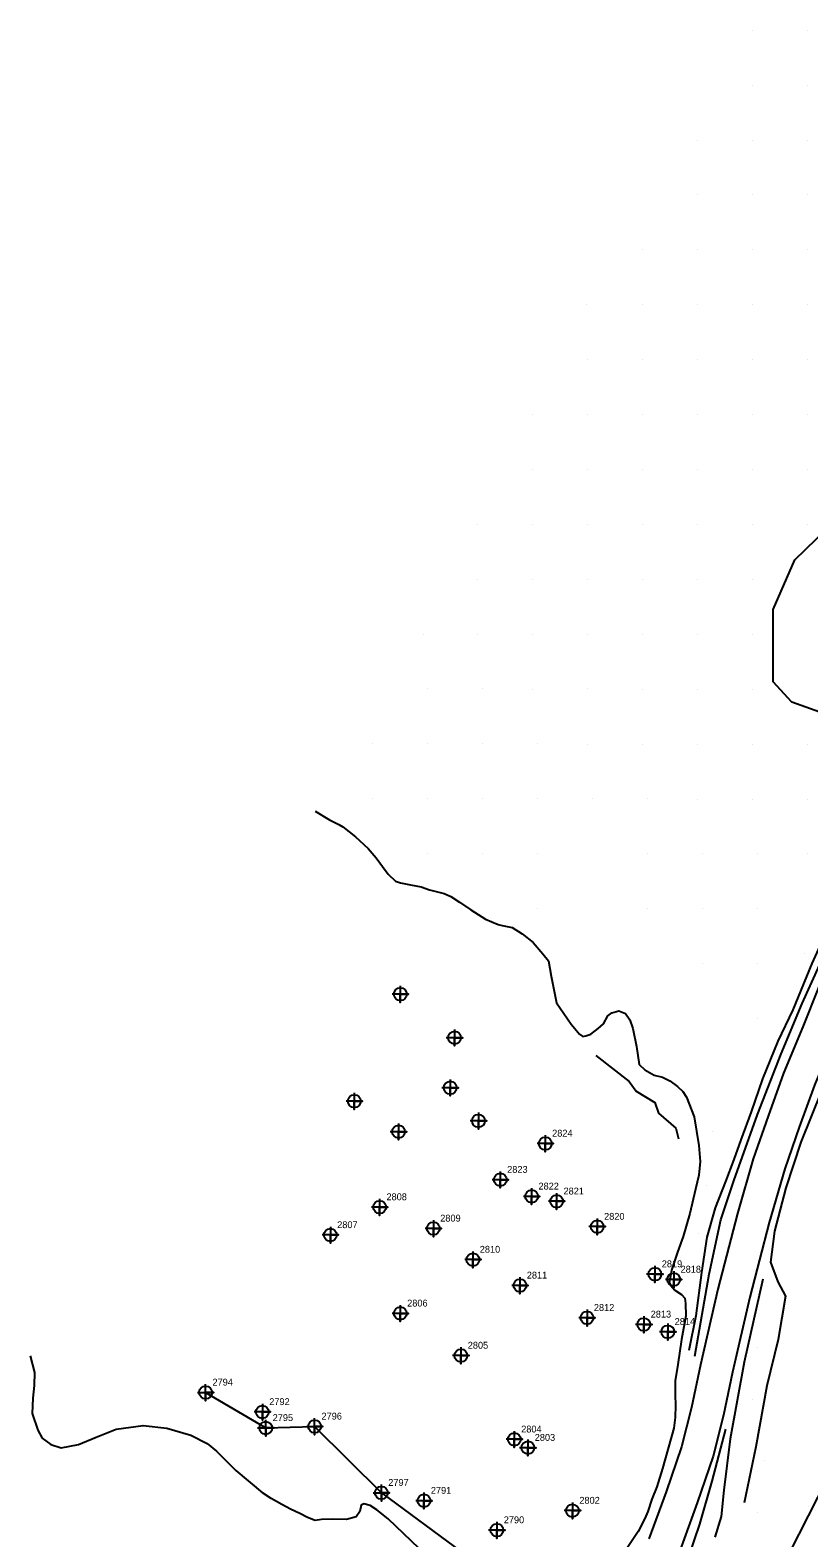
# Model space of a CAD drawing. Extents: x 2062781 to 2066835, y 358981 to 366501.
# Drawn here: x 2064554 to 2064838, y 362990 to 363540 of the extents above; entities that cross this region are included whole.
import ezdxf

# ---------------------------------------------------------------- set-up
doc = ezdxf.new("R2010")
doc.units = 0
for name, color, linetype in [('Exist DTM Regular Point CELL', 7, 'Continuous'), ('Exist DTM Regular Point Cogo Number', 7, 'Continuous'), ('Exist DTM Regular Point Underwater CELL', 7, 'Continuous'), ('Exist DTM Regular Point Underwater Cogo Number', 7, 'Continuous'), ('Exist Hydro Stream or Body of Water', 7, 'Continuous'), ('Exist Hydro Stream or Body of Water Cogo Number', 7, 'Continuous'), ('Exist Hydro Stream or Body of Water Cogo Point CELL', 7, 'Continuous'), ('Exist Structure Major Deck Tunnel Box Culvert', 7, 'Continuous'), ('PH Exist DTM Breakline', 7, 'Continuous'), ('PH Exist DTM Point', 7, 'Continuous')]:
    doc.layers.add(name, color=color, linetype=linetype)

msp = doc.modelspace()

# ---------------------------------------------------------------- linework, layer by layer
at = {"layer": 'Exist DTM Regular Point CELL'}
for points in [[(2064788.45, 363087.54), (2064788.45, 363081.54), (2064788.45, 363084.54), (2064791.45, 363084.54), (2064785.45, 363084.54)], [(2064786.3, 363068.49), (2064786.3, 363062.49), (2064786.3, 363065.49), (2064789.3, 363065.49), (2064783.3, 363065.49)]]:
    msp.add_lwpolyline(points, dxfattribs=at)
for centre in [(2064788.45, 363084.54), (2064786.3, 363065.49)]:
    msp.add_circle(centre, 2.34, dxfattribs=at)
at = {"layer": 'Exist DTM Regular Point Underwater CELL'}
for points in [[(2064688.89, 363191.46), (2064688.89, 363185.46), (2064688.89, 363188.46), (2064691.89, 363188.46), (2064685.89, 363188.46)], [(2064708.64, 363175.6), (2064708.64, 363169.6), (2064708.64, 363172.6), (2064711.64, 363172.6), (2064705.64, 363172.6)], [(2064707.05, 363157.38), (2064707.05, 363151.38), (2064707.05, 363154.38), (2064710.05, 363154.38), (2064704.05, 363154.38)], [(2064672.13, 363152.51), (2064672.13, 363146.51), (2064672.13, 363149.51), (2064675.13, 363149.51), (2064669.13, 363149.51)], [(2064717.35, 363145.34), (2064717.35, 363139.34), (2064717.35, 363142.34), (2064720.35, 363142.34), (2064714.35, 363142.34)], [(2064688.25, 363141.37), (2064688.25, 363135.37), (2064688.25, 363138.37), (2064691.25, 363138.37), (2064685.25, 363138.37)], [(2064741.68, 363137.09), (2064741.68, 363131.09), (2064741.68, 363134.09), (2064744.68, 363134.09), (2064738.68, 363134.09)], [(2064725.31, 363123.9), (2064725.31, 363117.9), (2064725.31, 363120.9), (2064728.31, 363120.9), (2064722.31, 363120.9)], [(2064736.7, 363117.82), (2064736.7, 363111.82), (2064736.7, 363114.82), (2064739.7, 363114.82), (2064733.7, 363114.82)], [(2064745.82, 363116.02), (2064745.82, 363110.02), (2064745.82, 363113.02), (2064748.82, 363113.02), (2064742.82, 363113.02)], [(2064681.35, 363113.92), (2064681.35, 363107.92), (2064681.35, 363110.92), (2064684.35, 363110.92), (2064678.35, 363110.92)], [(2064700.93, 363106.15), (2064700.93, 363100.15), (2064700.93, 363103.15), (2064703.93, 363103.15), (2064697.93, 363103.15)], [(2064760.6, 363106.8), (2064760.6, 363100.8), (2064760.6, 363103.8), (2064763.6, 363103.8), (2064757.6, 363103.8)], [(2064663.41, 363103.76), (2064663.41, 363097.76), (2064663.41, 363100.76), (2064666.41, 363100.76), (2064660.41, 363100.76)], [(2064715.33, 363094.8), (2064715.33, 363088.8), (2064715.33, 363091.8), (2064718.33, 363091.8), (2064712.33, 363091.8)], [(2064781.6, 363089.51), (2064781.6, 363083.51), (2064781.6, 363086.51), (2064784.6, 363086.51), (2064778.6, 363086.51)], [(2064732.45, 363085.39), (2064732.45, 363079.39), (2064732.45, 363082.39), (2064735.45, 363082.39), (2064729.45, 363082.39)], [(2064688.89, 363075.21), (2064688.89, 363069.21), (2064688.89, 363072.21), (2064691.89, 363072.21), (2064685.89, 363072.21)], [(2064756.88, 363073.61), (2064756.88, 363067.61), (2064756.88, 363070.61), (2064759.88, 363070.61), (2064753.88, 363070.61)], [(2064777.57, 363071.19), (2064777.57, 363065.19), (2064777.57, 363068.19), (2064780.57, 363068.19), (2064774.57, 363068.19)], [(2064710.95, 363059.86), (2064710.95, 363053.86), (2064710.95, 363056.86), (2064713.95, 363056.86), (2064707.95, 363056.86)], [(2064638.67, 363039.32), (2064638.67, 363033.32), (2064638.67, 363036.32), (2064641.67, 363036.32), (2064635.67, 363036.32)], [(2064730.41, 363029.35), (2064730.41, 363023.35), (2064730.41, 363026.35), (2064733.41, 363026.35), (2064727.41, 363026.35)], [(2064735.34, 363026.3), (2064735.34, 363020.3), (2064735.34, 363023.3), (2064738.34, 363023.3), (2064732.34, 363023.3)], [(2064697.51, 363007.01), (2064697.51, 363001.01), (2064697.51, 363004.01), (2064700.51, 363004.01), (2064694.51, 363004.01)], [(2064751.59, 363003.39), (2064751.59, 362997.39), (2064751.59, 363000.39), (2064754.59, 363000.39), (2064748.59, 363000.39)], [(2064724.06, 362996.29), (2064724.06, 362990.29), (2064724.06, 362993.29), (2064727.06, 362993.29), (2064721.06, 362993.29)]]:
    msp.add_lwpolyline(points, dxfattribs=at)
for centre in [(2064688.89, 363188.46), (2064708.64, 363172.6), (2064707.05, 363154.38), (2064672.13, 363149.51), (2064717.35, 363142.34), (2064688.25, 363138.37), (2064741.68, 363134.09), (2064725.31, 363120.9), (2064736.7, 363114.82), (2064745.82, 363113.02), (2064681.35, 363110.92), (2064700.93, 363103.15), (2064760.6, 363103.8), (2064663.41, 363100.76), (2064715.33, 363091.8), (2064781.6, 363086.51), (2064732.45, 363082.39), (2064688.89, 363072.21), (2064756.88, 363070.61), (2064777.57, 363068.19), (2064710.95, 363056.86), (2064638.67, 363036.32), (2064730.41, 363026.35), (2064735.34, 363023.3), (2064697.51, 363004.01), (2064751.59, 363000.39), (2064724.06, 362993.29)]:
    msp.add_circle(centre, 2.34, dxfattribs=at)
at = {"layer": 'Exist Hydro Stream or Body of Water'}
for points in [[(2064760.13, 363166.13), (2064772.23, 363156.64), (2064774.78, 363153.16), (2064781.59, 363149.01), (2064782.97, 363145.09), (2064789.28, 363139.67), (2064790.17, 363135.72)], [(2064617.98, 363043.42), (2064639.91, 363030.5), (2064657.69, 363031.04), (2064682, 363006.89), (2064711.34, 362985.3), (2064723.86, 362974.82), (2064739.34, 362964.04)]]:
    msp.add_lwpolyline(points, dxfattribs=at)
at = {"layer": 'Exist Hydro Stream or Body of Water Cogo Point CELL'}
for points in [[(2064614.98, 363043.42), (2064620.98, 363043.42), (2064617.98, 363043.42), (2064617.98, 363040.42), (2064617.98, 363046.42)], [(2064614.98, 363043.42), (2064620.98, 363043.42), (2064617.98, 363043.42), (2064617.98, 363040.42), (2064617.98, 363046.42)], [(2064614.98, 363043.42), (2064620.98, 363043.42), (2064617.98, 363043.42), (2064617.98, 363040.42), (2064617.98, 363046.42)], [(2064636.91, 363030.5), (2064642.91, 363030.5), (2064639.91, 363030.5), (2064639.91, 363027.5), (2064639.91, 363033.5)], [(2064636.91, 363030.5), (2064642.91, 363030.5), (2064639.91, 363030.5), (2064639.91, 363027.5), (2064639.91, 363033.5)], [(2064636.91, 363030.5), (2064642.91, 363030.5), (2064639.91, 363030.5), (2064639.91, 363027.5), (2064639.91, 363033.5)], [(2064654.69, 363031.04), (2064660.69, 363031.04), (2064657.69, 363031.04), (2064657.69, 363028.04), (2064657.69, 363034.04)], [(2064654.69, 363031.04), (2064660.69, 363031.04), (2064657.69, 363031.04), (2064657.69, 363028.04), (2064657.69, 363034.04)], [(2064654.69, 363031.04), (2064660.69, 363031.04), (2064657.69, 363031.04), (2064657.69, 363028.04), (2064657.69, 363034.04)], [(2064679, 363006.89), (2064685, 363006.89), (2064682, 363006.89), (2064682, 363003.89), (2064682, 363009.89)], [(2064679, 363006.89), (2064685, 363006.89), (2064682, 363006.89), (2064682, 363003.89), (2064682, 363009.89)], [(2064679, 363006.89), (2064685, 363006.89), (2064682, 363006.89), (2064682, 363003.89), (2064682, 363009.89)]]:
    msp.add_lwpolyline(points, dxfattribs=at)
for centre in [(2064617.98, 363043.42), (2064617.98, 363043.42), (2064617.98, 363043.42), (2064639.91, 363030.5), (2064639.91, 363030.5), (2064639.91, 363030.5), (2064657.69, 363031.04), (2064657.69, 363031.04), (2064657.69, 363031.04), (2064682, 363006.89), (2064682, 363006.89), (2064682, 363006.89)]:
    msp.add_circle(centre, 2.34, dxfattribs=at)
at = {"layer": 'Exist Structure Major Deck Tunnel Box Culvert'}
msp.add_lwpolyline([(2064623.4, 362577.44), (2064650.62, 362630.92), (2064677.82, 362684.31), (2064698.23, 362724.56), (2064718.6, 362764.59), (2064738.99, 362804.71), (2064759.36, 362844.81), (2064779.84, 362884.94), (2064800.12, 362924.98), (2064820.56, 362965.07), (2064840.94, 363005.22), (2064861.36, 363045.25), (2064881.68, 363085.34), (2064902.1, 363125.46), (2064922.64, 363165.68)], dxfattribs=at)
at = {"layer": 'PH Exist DTM Breakline'}
for points in [[(2064843.33, 363290.6), (2064831.49, 363294.81), (2064824.68, 363302.18), (2064824.62, 363328.54), (2064832.53, 363346.69), (2064844.5, 363358.16)], [(2064657.92, 363255.13), (2064663.09, 363251.94), (2064666.55, 363250.21), (2064667.94, 363249.45), (2064672.63, 363245.78), (2064677.14, 363241.5), (2064680.09, 363238.15), (2064682.43, 363234.95), (2064684.41, 363232.16), (2064687.1, 363229.67), (2064689.01, 363228.99), (2064692.59, 363228.3), (2064696.52, 363227.55), (2064699.57, 363226.47), (2064704.82, 363225.15), (2064707.28, 363224.04), (2064710.44, 363221.98), (2064714.59, 363219.2), (2064719.91, 363215.83), (2064724.51, 363213.84), (2064725.99, 363213.41), (2064729.67, 363212.71), (2064733.32, 363210.38), (2064737.29, 363207.26), (2064740.76, 363203.11), (2064742.81, 363200.63), (2064743.84, 363194.98), (2064745.82, 363185.25), (2064751.16, 363177.59), (2064754.2, 363173.91), (2064755.33, 363173.09), (2064756.45, 363173.32), (2064758.25, 363173.95), (2064760.92, 363175.9), (2064762.83, 363177.68), (2064764.48, 363180.52), (2064765.95, 363181.68), (2064768.48, 363182.37), (2064770.87, 363181.41), (2064772.48, 363179.06), (2064773.6, 363175.9), (2064774.95, 363169.35), (2064775.92, 363162.85), (2064777.92, 363160.93), (2064781.3, 363158.95), (2064784.4, 363158.25), (2064787.04, 363156.88), (2064789.83, 363154.89), (2064791.73, 363153.06), (2064793.05, 363150.99), (2064795.86, 363143.75), (2064797.66, 363133.36), (2064798.12, 363127.49), (2064797.54, 363122.52), (2064796.33, 363117.48), (2064794.31, 363108.61), (2064791.88, 363100.18), (2064789.87, 363094.56), (2064787.72, 363088.34), (2064786.85, 363083.47), (2064787.46, 363082.36), (2064788.87, 363080.66), (2064791.24, 363079.11), (2064792.48, 363077.7), (2064792.79, 363075.86), (2064792.91, 363071.27), (2064791.34, 363062.69), (2064789.94, 363053.64), (2064789.04, 363047.69), (2064789.03, 363042.51), (2064789.08, 363038.62), (2064788.93, 363034.34), (2064788.48, 363030.46), (2064784.35, 363015.67), (2064782.35, 363009.03), (2064780.47, 363004.5), (2064779.02, 363000.05), (2064777.89, 362997.57), (2064775.49, 362992.81), (2064770.64, 362985.56)], [(2064862.71, 363237.07), (2064853.51, 363218.29), (2064848.01, 363206.24), (2064841.2, 363190.87), (2064835.47, 363176.54), (2064828.48, 363159.64), (2064822.82, 363144.06), (2064817.42, 363128.52), (2064811.62, 363108.55), (2064804.49, 363081.02), (2064798.19, 363053.42), (2064794.93, 363037.88), (2064791.27, 363023.67), (2064785.71, 363007.19), (2064779.45, 362990.06)], [(2064873.49, 363231.78), (2064864.35, 363213.16), (2064858.95, 363201.32), (2064852.26, 363186.21), (2064846.59, 363172.02), (2064839.67, 363155.29), (2064834.13, 363140.04), (2064828.86, 363124.88), (2064823.2, 363105.37), (2064816.15, 363078.18), (2064809.91, 363050.85), (2064806.62, 363035.15), (2064802.78, 363020.25), (2064797.04, 363003.22), (2064790.66, 362985.76)], [(2064853.69, 363231.16), (2064846.39, 363216.49), (2064838.69, 363199.61), (2064831.8, 363182.7), (2064826.4, 363171.33), (2064820.73, 363157.67), (2064816.63, 363145.64), (2064812.94, 363135.45), (2064810.32, 363128.26), (2064807.3, 363120.23), (2064803.49, 363110.63), (2064800.46, 363099.95), (2064798.58, 363087.12), (2064796.5, 363071.29), (2064793.9, 363058.66)], [(2064796.12, 363056.59), (2064801.37, 363086.52), (2064805.6, 363106.33), (2064810.36, 363120.49), (2064819, 363144.64), (2064827.58, 363166.72), (2064835.24, 363185.04), (2064841.66, 363199.26), (2064848.43, 363213.73), (2064855.43, 363227.48)], [(2064871.4, 363223.84), (2064863.73, 363207.42), (2064856.68, 363192.23), (2064849.57, 363172.94), (2064842.21, 363153.26), (2064834.74, 363134.62), (2064829.26, 363117.95), (2064825.16, 363102.2), (2064823.75, 363090.82), (2064826.39, 363083.66), (2064829.2, 363078.52), (2064826.43, 363062.75), (2064822.32, 363045.89), (2064818.41, 363023.67), (2064814.05, 363003.28)], [(2064820.94, 363084.71), (2064814.16, 363054.4), (2064809.06, 363026.54), (2064806.69, 363007.85), (2064805.77, 362998.28), (2064803.47, 362990.71)], [(2064554.1, 363056.73), (2064555.71, 363050.64), (2064555.55, 363046.01), (2064555.05, 363041.31), (2064554.89, 363035.71), (2064556.87, 363029.74), (2064558.43, 363026.8), (2064561.63, 363024.44), (2064565.35, 363023.22), (2064571.7, 363024.51), (2064578.18, 363027.14), (2064585.47, 363030.04), (2064595.28, 363031.4), (2064603.88, 363030.39), (2064612.56, 363027.86), (2064618.61, 363024.84), (2064621.96, 363022.04), (2064628.95, 363014.99), (2064638.74, 363006.82)], [(2064807.3, 363030.11), (2064802.32, 363011.11), (2064797.84, 362995.47), (2064791.78, 362977.67), (2064781.44, 362953.56), (2064768.13, 362924.72), (2064754.4, 362897.09), (2064735.4, 362860.89), (2064708.55, 362807.94), (2064678.24, 362751.31), (2064659.16, 362714.52), (2064643.7, 362686.38), (2064628.13, 362658.09), (2064617.21, 362639.02), (2064609.98, 362625.86), (2064598.02, 362605.33), (2064591.98, 362596.35), (2064587.07, 362588.82), (2064583.37, 362583.25)], [(2064695.66, 362986.75), (2064690.17, 362991.9), (2064684.52, 362997.38), (2064680.32, 363000.7), (2064677.93, 363002.22), (2064675.62, 363002.84), (2064674.61, 363002.33), (2064674.15, 363000.09), (2064672.83, 362998.15), (2064669.24, 362997.15), (2064664.17, 362997.23), (2064660.24, 362997.13), (2064657.92, 362996.75), (2064655.06, 362997.83), (2064652.6, 362999.16), (2064648.96, 363000.86), (2064645.77, 363002.62), (2064641.9, 363004.81), (2064638.74, 363006.82)]]:
    msp.add_lwpolyline(points, dxfattribs=at)
at = {"layer": 'PH Exist DTM Point'}
for p, q in [((2064817.11, 363539.52), (2064817.11, 363539.52)), ((2064837.11, 363539.52), (2064837.11, 363539.52)), ((2064817.11, 363519.52), (2064817.11, 363519.52)), ((2064837.11, 363519.52), (2064837.11, 363519.52)), ((2064797.11, 363499.52), (2064797.11, 363499.52)), ((2064817.11, 363499.52), (2064817.11, 363499.52)), ((2064837.11, 363499.52), (2064837.11, 363499.52)), ((2064797.11, 363479.52), (2064797.11, 363479.52)), ((2064817.06, 363479.61), (2064817.06, 363479.61)), ((2064837.11, 363479.52), (2064837.11, 363479.52)), ((2064777.11, 363459.52), (2064777.11, 363459.52)), ((2064797.11, 363459.52), (2064797.11, 363459.52)), ((2064817.11, 363459.52), (2064817.11, 363459.52)), ((2064837.11, 363459.52), (2064837.11, 363459.52)), ((2064756.69, 363439.7), (2064756.69, 363439.7)), ((2064777.11, 363439.52), (2064777.11, 363439.52)), ((2064797.11, 363439.52), (2064797.11, 363439.52)), ((2064817.11, 363439.52), (2064817.11, 363439.52)), ((2064837.11, 363439.52), (2064837.11, 363439.52)), ((2064757.11, 363419.52), (2064757.11, 363419.52)), ((2064777.11, 363419.52), (2064777.11, 363419.52)), ((2064797.11, 363419.52), (2064797.11, 363419.52)), ((2064817.11, 363419.52), (2064817.11, 363419.52)), ((2064837.11, 363419.52), (2064837.11, 363419.52)), ((2064736.97, 363399.72), (2064736.97, 363399.72)), ((2064757.11, 363399.52), (2064757.11, 363399.52)), ((2064777.11, 363399.52), (2064777.11, 363399.52)), ((2064797.11, 363399.52), (2064797.11, 363399.52)), ((2064817.11, 363399.52), (2064817.11, 363399.52)), ((2064837.16, 363399.52), (2064837.16, 363399.52)), ((2064737.16, 363379.62), (2064737.16, 363379.62)), ((2064757.11, 363379.52), (2064757.11, 363379.52)), ((2064777.11, 363379.52), (2064777.11, 363379.52)), ((2064797.11, 363379.52), (2064797.11, 363379.52)), ((2064817.11, 363379.52), (2064817.11, 363379.52)), ((2064837.11, 363379.52), (2064837.11, 363379.52)), ((2064717.11, 363359.52), (2064717.11, 363359.52)), ((2064737.11, 363359.52), (2064737.11, 363359.52)), ((2064757.11, 363359.52), (2064757.11, 363359.52)), ((2064777.11, 363359.52), (2064777.11, 363359.52)), ((2064797.11, 363359.52), (2064797.11, 363359.52)), ((2064817.11, 363359.52), (2064817.11, 363359.52)), ((2064837.11, 363359.52), (2064837.11, 363359.52)), ((2064717.11, 363339.52), (2064717.11, 363339.52)), ((2064737.11, 363339.52), (2064737.11, 363339.52)), ((2064757.11, 363339.52), (2064757.11, 363339.52)), ((2064777.11, 363339.52), (2064777.11, 363339.52)), ((2064797.11, 363339.52), (2064797.11, 363339.52)), ((2064817.11, 363339.52), (2064817.11, 363339.52)), ((2064697.25, 363319.57), (2064697.25, 363319.57)), ((2064717.11, 363319.52), (2064717.11, 363319.52)), ((2064737.11, 363319.52), (2064737.11, 363319.52)), ((2064757.11, 363319.52), (2064757.11, 363319.52)), ((2064777.11, 363319.52), (2064777.11, 363319.52)), ((2064797.11, 363319.52), (2064797.11, 363319.52)), ((2064817.11, 363319.52), (2064817.11, 363319.52)), ((2064698.86, 363299.76), (2064698.86, 363299.76)), ((2064718.86, 363299.76), (2064718.86, 363299.76)), ((2064737.11, 363299.52), (2064737.11, 363299.52)), ((2064757.04, 363299.62), (2064757.04, 363299.62)), ((2064777.11, 363299.52), (2064777.11, 363299.52)), ((2064797.11, 363299.52), (2064797.11, 363299.52)), ((2064817.12, 363299.55), (2064817.12, 363299.55)), ((2064678.8, 363279.74), (2064678.8, 363279.74)), ((2064698.86, 363279.76), (2064698.86, 363279.76)), ((2064718.86, 363279.76), (2064718.86, 363279.76)), ((2064738.86, 363279.76), (2064738.86, 363279.76)), ((2064757.11, 363279.52), (2064757.11, 363279.52)), ((2064777.11, 363279.52), (2064777.11, 363279.52)), ((2064797.11, 363279.52), (2064797.11, 363279.52)), ((2064817.11, 363279.52), (2064817.11, 363279.52)), ((2064837.11, 363279.52), (2064837.11, 363279.52)), ((2064678.79, 363259.79), (2064678.79, 363259.79)), ((2064698.86, 363259.76), (2064698.86, 363259.76)), ((2064718.84, 363259.72), (2064718.84, 363259.72)), ((2064738.86, 363259.76), (2064738.86, 363259.76)), ((2064758.86, 363259.76), (2064758.86, 363259.76)), ((2064778.86, 363259.76), (2064778.86, 363259.76)), ((2064797.11, 363259.52), (2064797.11, 363259.52)), ((2064817.11, 363259.52), (2064817.11, 363259.52)), ((2064837.11, 363259.52), (2064837.11, 363259.52)), ((2064698.86, 363239.76), (2064698.86, 363239.76)), ((2064718.86, 363239.76), (2064718.86, 363239.76)), ((2064738.86, 363239.76), (2064738.86, 363239.76)), ((2064778.86, 363239.76), (2064778.86, 363239.76)), ((2064798.86, 363239.76), (2064798.86, 363239.76)), ((2064818.86, 363239.76), (2064818.86, 363239.76)), ((2064837.11, 363239.52), (2064837.11, 363239.52)), ((2064738.86, 363219.76), (2064738.86, 363219.76)), ((2064778.86, 363219.76), (2064778.86, 363219.76)), ((2064798.86, 363219.76), (2064798.86, 363219.76)), ((2064818.86, 363219.76), (2064818.86, 363219.76)), ((2064835.95, 363203.18), (2064835.95, 363203.18)), ((2064798.86, 363199.76), (2064798.86, 363199.76)), ((2064818.86, 363199.76), (2064818.86, 363199.76)), ((2064818.82, 363179.78), (2064818.82, 363179.78)), ((2064802.66, 363138.51), (2064802.66, 363138.51)), ((2064800.44, 363118.65), (2064800.44, 363118.65)), ((2064797.44, 363101.38), (2064797.44, 363101.38)), ((2064818.86, 363059.76), (2064818.86, 363059.76)), ((2064817.11, 363040.82), (2064817.11, 363040.82)), ((2064821.54, 363018.69), (2064821.54, 363018.69)), ((2064818.86, 362999.76), (2064818.86, 362999.76)), ((2064837.38, 363001.93), (2064837.38, 363001.93))]:
    msp.add_line(p, q, dxfattribs=at)

# ---------------------------------------------------------------- texts
at = {"layer": 'Exist DTM Regular Point Cogo Number'}
for s, p in [('2818', (2064790.95, 363087.04)), ('2818', (2064790.95, 363087.04)), ('2818', (2064790.95, 363087.04)), ('2814', (2064788.8, 363067.99)), ('2814', (2064788.8, 363067.99)), ('2814', (2064788.8, 363067.99))]:
    msp.add_text(s, height=2.5, dxfattribs=at).set_placement(p)
at = {"layer": 'Exist DTM Regular Point Underwater Cogo Number'}
for s, p in [('2824', (2064744.18, 363136.59)), ('2824', (2064744.18, 363136.59)), ('2824', (2064744.18, 363136.59)), ('2823', (2064727.81, 363123.4)), ('2823', (2064727.81, 363123.4)), ('2823', (2064727.81, 363123.4)), ('2808', (2064683.85, 363113.42)), ('2808', (2064683.85, 363113.42)), ('2808', (2064683.85, 363113.42)), ('2822', (2064739.2, 363117.32)), ('2822', (2064739.2, 363117.32)), ('2822', (2064739.2, 363117.32)), ('2821', (2064748.32, 363115.52)), ('2821', (2064748.32, 363115.52)), ('2821', (2064748.32, 363115.52)), ('2807', (2064665.91, 363103.26)), ('2807', (2064665.91, 363103.26)), ('2807', (2064665.91, 363103.26)), ('2809', (2064703.43, 363105.65)), ('2809', (2064703.43, 363105.65)), ('2809', (2064703.43, 363105.65)), ('2820', (2064763.1, 363106.3)), ('2820', (2064763.1, 363106.3)), ('2820', (2064763.1, 363106.3)), ('2810', (2064717.83, 363094.3)), ('2810', (2064717.83, 363094.3)), ('2810', (2064717.83, 363094.3)), ('2819', (2064784.1, 363089.01)), ('2819', (2064784.1, 363089.01)), ('2819', (2064784.1, 363089.01)), ('2811', (2064734.95, 363084.89)), ('2811', (2064734.95, 363084.89)), ('2811', (2064734.95, 363084.89)), ('2806', (2064691.39, 363074.71)), ('2806', (2064691.39, 363074.71)), ('2806', (2064691.39, 363074.71)), ('2812', (2064759.38, 363073.11)), ('2812', (2064759.38, 363073.11)), ('2812', (2064759.38, 363073.11)), ('2813', (2064780.07, 363070.69)), ('2813', (2064780.07, 363070.69)), ('2813', (2064780.07, 363070.69)), ('2805', (2064713.45, 363059.36)), ('2805', (2064713.45, 363059.36)), ('2805', (2064713.45, 363059.36)), ('2792', (2064641.17, 363038.82)), ('2792', (2064641.17, 363038.82)), ('2792', (2064641.17, 363038.82)), ('2804', (2064732.91, 363028.85)), ('2804', (2064732.91, 363028.85)), ('2804', (2064732.91, 363028.85)), ('2803', (2064737.84, 363025.8)), ('2803', (2064737.84, 363025.8)), ('2803', (2064737.84, 363025.8)), ('2791', (2064700.01, 363006.51)), ('2791', (2064700.01, 363006.51)), ('2791', (2064700.01, 363006.51)), ('2802', (2064754.09, 363002.89)), ('2802', (2064754.09, 363002.89)), ('2802', (2064754.09, 363002.89)), ('2790', (2064726.56, 362995.79)), ('2790', (2064726.56, 362995.79)), ('2790', (2064726.56, 362995.79))]:
    msp.add_text(s, height=2.5, dxfattribs=at).set_placement(p)
at = {"layer": 'Exist Hydro Stream or Body of Water Cogo Number'}
for s, p in [('2794', (2064620.48, 363045.92)), ('2794', (2064620.48, 363045.92)), ('2794', (2064620.48, 363045.92)), ('2795', (2064642.41, 363033)), ('2795', (2064642.41, 363033)), ('2795', (2064642.41, 363033)), ('2796', (2064660.19, 363033.54)), ('2796', (2064660.19, 363033.54)), ('2796', (2064660.19, 363033.54)), ('2797', (2064684.5, 363009.39)), ('2797', (2064684.5, 363009.39)), ('2797', (2064684.5, 363009.39))]:
    msp.add_text(s, height=2.5, dxfattribs=at).set_placement(p)

doc.saveas('drawing.dxf')
